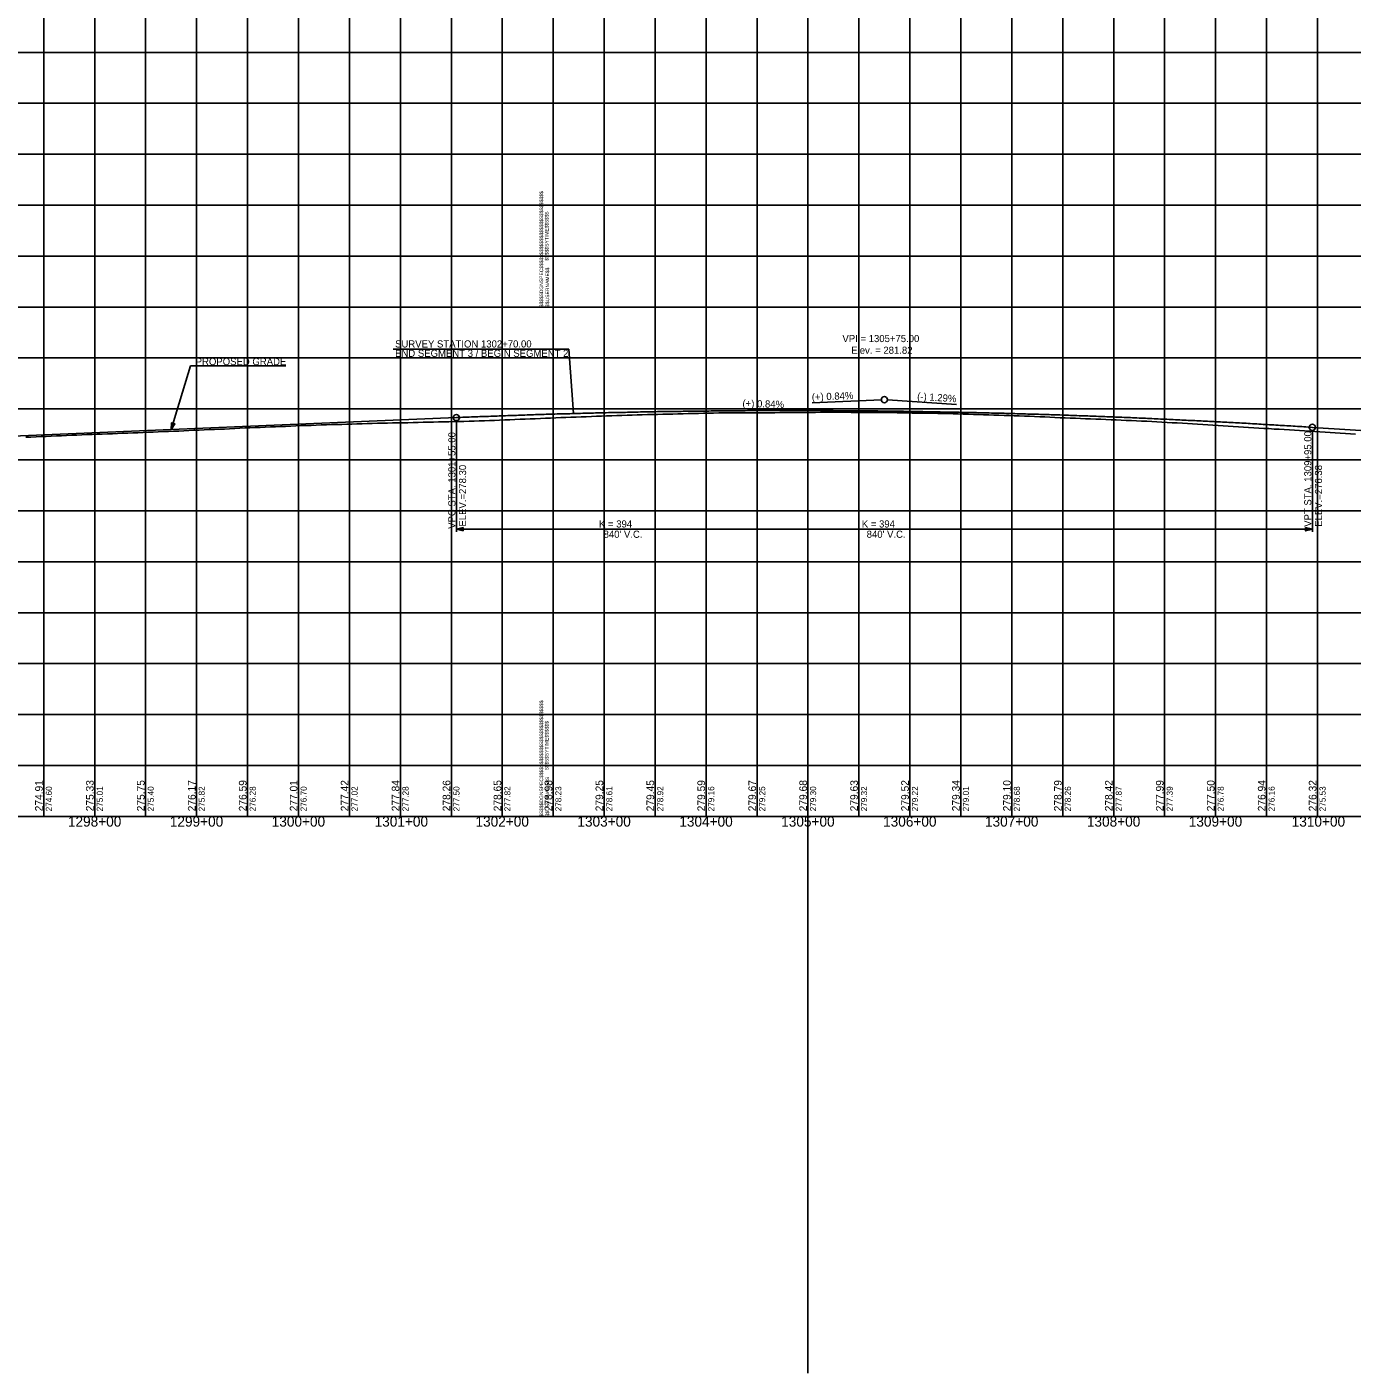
# Model space of a CAD drawing. Extents: x -90830 to 2015517, y -20856 to 836331.
# Drawn here: x 18657 to 19957, y -11344 to -10022 of the extents above; entities that cross this region are included whole.
import ezdxf

# ---------------------------------------------------------------- set-up
doc = ezdxf.new("R2010")
doc.units = 0
for name, color, linetype in [('Level 1', 7, 'Continuous'), ('RD_DDB_GradeTX', 7, 'Continuous'), ('RD_DDB_Profile_Elev', 7, 'Continuous'), ('RD_DDB_Profile_EX', 7, 'Continuous'), ('RD_DDB_Profile_Lbl', 7, 'Continuous'), ('RD_DDB_Profile_PR', 7, 'Continuous'), ('RD_DDB_StaTX', 7, 'Continuous'), ('RD_DDB_StripGrade', 7, 'Continuous'), ('RD_DDB_VCLbl', 7, 'Continuous'), ('RD_GPK_Profile_Cell', 7, 'Continuous'), ('RD_PD_Final_TX', 7, 'Continuous'), ('RD_TX_Drainage', 7, 'Continuous')]:
    doc.layers.add(name, color=color, linetype=linetype)

msp = doc.modelspace()

# ---------------------------------------------------------------- linework, layer by layer
at = {"layer": 'Level 1'}
for p, q in [((19423.5, -3180.8), (19423.5, -11343.5)), ((18673.5, -9797.1), (18673.5, -10297.1)), ((18723.5, -9797.1), (18723.5, -10297.1)), ((18773.5, -9797.1), (18773.5, -10297.1)), ((18823.5, -9797.1), (18823.5, -10297.1)), ((18873.5, -9797.1), (18873.5, -10297.1)), ((18923.5, -9797.1), (18923.5, -10297.1)), ((18973.5, -9797.1), (18973.5, -10297.1)), ((19023.5, -9797.1), (19023.5, -10297.1)), ((19073.5, -9797.1), (19073.5, -10297.1)), ((19123.5, -9797.1), (19123.5, -10297.1)), ((19173.5, -9797.1), (19173.5, -10297.1)), ((19173.5, -9797.1), (19173.5, -10297.1)), ((19173.5, -9797.1), (19173.5, -10297.1)), ((19223.5, -9797.1), (19223.5, -10297.1)), ((19273.5, -9797.1), (19273.5, -10297.1)), ((19323.5, -9797.1), (19323.5, -10297.1)), ((19373.5, -9797.1), (19373.5, -10297.1)), ((19423.5, -9797.1), (19423.5, -10297.1)), ((19473.5, -9797.1), (19473.5, -10297.1)), ((19523.5, -9797.1), (19523.5, -10297.1)), ((19573.5, -9797.1), (19573.5, -10297.1)), ((19623.5, -9797.1), (19623.5, -10297.1)), ((19673.5, -9797.1), (19673.5, -10297.1)), ((19723.5, -9797.1), (19723.5, -10297.1)), ((19773.5, -9797.1), (19773.5, -10297.1)), ((19823.5, -9797.1), (19823.5, -10297.1)), ((19873.5, -9797.1), (19873.5, -10297.1)), ((19923.5, -9797.1), (19923.5, -10297.1)), ((17573.5, -10047.1), (19173.5, -10047.1)), ((19173.5, -10047.1), (20773.5, -10047.1)), ((17573.5, -10097.1), (19173.5, -10097.1)), ((19173.5, -10097.1), (20773.5, -10097.1)), ((17573.5, -10147.1), (19173.5, -10147.1)), ((19173.5, -10147.1), (20773.5, -10147.1)), ((17573.5, -10197.1), (19173.5, -10197.1)), ((19173.5, -10197.1), (20773.5, -10197.1)), ((17573.5, -10247.1), (19173.5, -10247.1)), ((19173.5, -10247.1), (20773.5, -10247.1)), ((17573.5, -10297.1), (19173.5, -10297.1)), ((17573.5, -10297.1), (19173.5, -10297.1)), ((18673.5, -10297.1), (18673.5, -10797.1)), ((18723.5, -10297.1), (18723.5, -10797.1)), ((18773.5, -10297.1), (18773.5, -10797.1)), ((18823.5, -10297.1), (18823.5, -10797.1)), ((18873.5, -10297.1), (18873.5, -10797.1)), ((18923.5, -10297.1), (18923.5, -10797.1)), ((18973.5, -10297.1), (18973.5, -10797.1)), ((19023.5, -10297.1), (19023.5, -10797.1)), ((19073.5, -10297.1), (19073.5, -10797.1)), ((19123.5, -10297.1), (19123.5, -10797.1)), ((19173.5, -10297.1), (20773.5, -10297.1)), ((19173.5, -10297.1), (19173.5, -10797.1)), ((19173.5, -10297.1), (19173.5, -10797.1)), ((19173.5, -10297.1), (20773.5, -10297.1)), ((19173.5, -10297.1), (19173.5, -10797.1)), ((19223.5, -10297.1), (19223.5, -10797.1)), ((19273.5, -10297.1), (19273.5, -10797.1)), ((19323.5, -10297.1), (19323.5, -10797.1)), ((19373.5, -10297.1), (19373.5, -10797.1)), ((19423.5, -10297.1), (19423.5, -10797.1)), ((19473.5, -10297.1), (19473.5, -10797.1)), ((19523.5, -10297.1), (19523.5, -10797.1)), ((19573.5, -10297.1), (19573.5, -10797.1)), ((19623.5, -10297.1), (19623.5, -10797.1)), ((19673.5, -10297.1), (19673.5, -10797.1)), ((19723.5, -10297.1), (19723.5, -10797.1)), ((19773.5, -10297.1), (19773.5, -10797.1)), ((19823.5, -10297.1), (19823.5, -10797.1)), ((19873.5, -10297.1), (19873.5, -10797.1)), ((19923.5, -10297.1), (19923.5, -10797.1)), ((17573.5, -10347.1), (19173.5, -10347.1)), ((19173.5, -10347.1), (20773.5, -10347.1)), ((17573.5, -10397.1), (19173.5, -10397.1)), ((19173.5, -10397.1), (20773.5, -10397.1)), ((17573.5, -10447.1), (19173.5, -10447.1)), ((19173.5, -10447.1), (20773.5, -10447.1)), ((17573.5, -10497.1), (19173.5, -10497.1)), ((19173.5, -10497.1), (20773.5, -10497.1)), ((17573.5, -10547.1), (19173.5, -10547.1)), ((19173.5, -10547.1), (20773.5, -10547.1)), ((17573.5, -10597.1), (19173.5, -10597.1)), ((19173.5, -10597.1), (20773.5, -10597.1)), ((17573.5, -10647.1), (19173.5, -10647.1)), ((19173.5, -10647.1), (20773.5, -10647.1)), ((17573.5, -10697.1), (19173.5, -10697.1)), ((19173.5, -10697.1), (20773.5, -10697.1)), ((17573.5, -10747.1), (19173.5, -10747.1)), ((19173.5, -10747.1), (20773.5, -10747.1)), ((17573.5, -10797.1), (19173.5, -10797.1)), ((19173.5, -10797.1), (20773.5, -10797.1))]:
    msp.add_line(p, q, dxfattribs=at)
at = {"layer": 'RD_DDB_GradeTX'}
for p, q in [((19427.5, -10391), (19495.5, -10388.1)), ((19569.3, -10392.6), (19501.5, -10388.2))]:
    msp.add_line(p, q, dxfattribs=at)
msp.add_circle((19498.5, -10388), 3, dxfattribs=at)
at = {"layer": 'RD_DDB_Profile_EX'}
for points in [[(18655.9, -10424.9), (18660.9, -10424.7), (18665.9, -10424.4), (18670.9, -10424.2), (18675.9, -10424), (18680.9, -10423.8), (18685.9, -10423.6), (18690.9, -10423.4), (18695.9, -10423.2), (18700.9, -10422.9), (18705.9, -10422.7), (18710.9, -10422.5), (18715.9, -10422.3), (18720.9, -10422.1), (18725.9, -10422), (18730.9, -10421.8), (18735.9, -10421.6), (18740.9, -10421.4), (18745.9, -10421.2), (18750.9, -10421), (18755.9, -10420.8), (18760.9, -10420.6), (18765.9, -10420.4), (18770.9, -10420.2), (18775.9, -10420), (18780.9, -10419.8), (18785.9, -10419.6), (18790.9, -10419.4), (18795.9, -10419.2), (18800.9, -10419), (18805.9, -10418.8), (18810.9, -10418.6), (18815.9, -10418.4), (18820.9, -10418.1), (18825.9, -10417.9), (18830.9, -10417.7), (18835.9, -10417.4), (18840.9, -10417.2), (18845.9, -10417), (18850.9, -10416.8), (18855.9, -10416.5), (18860.9, -10416.3), (18865.9, -10416.1), (18870.9, -10415.8), (18875.9, -10415.6), (18880.9, -10415.4), (18885.9, -10415.2), (18890.9, -10415), (18895.9, -10414.8), (18900.9, -10414.6), (18905.9, -10414.4), (18910.9, -10414.2), (18915.9, -10413.9), (18920.9, -10413.7), (18925.9, -10413.5), (18930.9, -10413.3), (18935.9, -10413.2), (18940.9, -10413), (18945.9, -10412.8), (18950.9, -10412.7), (18955.9, -10412.5), (18960.9, -10412.4), (18965.9, -10412.3), (18970.9, -10412.1), (18975.9, -10412), (18980.9, -10411.8), (18985.9, -10411.6), (18990.9, -10411.5), (18995.9, -10411.3), (19000.9, -10411.2), (19005.9, -10411.1), (19010.9, -10411), (19015.9, -10410.9), (19020.9, -10410.8), (19025.9, -10410.7), (19030.9, -10410.6), (19035.9, -10410.5), (19040.9, -10410.3), (19045.9, -10410.2)], [(19045.9, -10410.2), (19050.9, -10410.1), (19055.9, -10410), (19060.9, -10409.9), (19065.9, -10409.8), (19070.9, -10409.7), (19075.9, -10409.5), (19080.9, -10409.4), (19085.9, -10409.3), (19090.9, -10409.2), (19095.9, -10409.1), (19100.9, -10408.9), (19105.9, -10408.7), (19110.9, -10408.6), (19115.9, -10408.3), (19120.9, -10408.1), (19125.9, -10407.9), (19130.9, -10407.7), (19135.9, -10407.5), (19140.9, -10407.3), (19145.9, -10407.1), (19150.9, -10406.9), (19155.9, -10406.7), (19160.9, -10406.5), (19165.9, -10406.3), (19170.9, -10406.1), (19175.9, -10405.8), (19180.9, -10405.6), (19185.9, -10405.4), (19190.9, -10405.2), (19195.9, -10405.1), (19200.9, -10405), (19205.9, -10404.8), (19210.9, -10404.5), (19215.9, -10404.3), (19220.9, -10404.1), (19225.9, -10404), (19230.9, -10403.8), (19235.9, -10403.6), (19240.9, -10403.5), (19245.9, -10403.3), (19250.9, -10403.1), (19255.9, -10403), (19260.9, -10402.9), (19265.9, -10402.7), (19270.9, -10402.6), (19275.9, -10402.5), (19280.9, -10402.3), (19285.9, -10402.2), (19290.9, -10402.1), (19295.9, -10402), (19300.9, -10401.8), (19305.9, -10401.7), (19310.9, -10401.6), (19315.9, -10401.5), (19320.9, -10401.3), (19325.9, -10401.2), (19330.9, -10401.1), (19335.9, -10401), (19340.9, -10401), (19345.9, -10400.9), (19350.9, -10400.8), (19355.9, -10400.8), (19360.9, -10400.8), (19365.9, -10400.8), (19370.9, -10400.9), (19375.9, -10400.9), (19380.9, -10400.9), (19385.9, -10400.8), (19390.9, -10400.8), (19395.9, -10400.7), (19400.9, -10400.7), (19405.9, -10400.7), (19410.9, -10400.7), (19415.9, -10400.7), (19420.9, -10400.6), (19425.9, -10400.6), (19430.9, -10400.5), (19435.9, -10400.4), (19440.9, -10400.4), (19445.9, -10400.4), (19450.9, -10400.4), (19455.9, -10400.4), (19460.9, -10400.4), (19465.9, -10400.5), (19470.9, -10400.5), (19475.9, -10400.5), (19480.9, -10400.5), (19485.9, -10400.6), (19490.9, -10400.6), (19495.9, -10400.6), (19500.9, -10400.7), (19505.9, -10400.7), (19510.9, -10400.8), (19515.9, -10400.9), (19520.9, -10401), (19525.9, -10401.1), (19530.9, -10401.1), (19535.9, -10401.2), (19540.9, -10401.3), (19545.9, -10401.4)], [(19545.9, -10401.4), (19550.9, -10401.5), (19555.9, -10401.6), (19560.9, -10401.7), (19565.9, -10401.9), (19570.9, -10402), (19575.9, -10402.2), (19580.9, -10402.3), (19585.9, -10402.5), (19590.9, -10402.7), (19595.9, -10402.9), (19600.9, -10403), (19605.9, -10403.2), (19610.9, -10403.3), (19615.9, -10403.5), (19620.9, -10403.6), (19625.9, -10403.8), (19630.9, -10404), (19635.9, -10404.2), (19640.9, -10404.3), (19645.9, -10404.6), (19650.9, -10404.8), (19655.9, -10405), (19660.9, -10405.2), (19665.9, -10405.4), (19670.9, -10405.7), (19675.9, -10405.9), (19680.9, -10406.1), (19685.9, -10406.3), (19690.9, -10406.5), (19695.9, -10406.7), (19700.9, -10406.9), (19705.9, -10407.1), (19710.9, -10407.3), (19715.9, -10407.5), (19720.9, -10407.7), (19725.9, -10407.9), (19730.9, -10408.1), (19735.9, -10408.3), (19740.9, -10408.5), (19745.9, -10408.7), (19750.9, -10409), (19755.9, -10409.2), (19760.9, -10409.5), (19765.9, -10409.7), (19770.9, -10410), (19775.9, -10410.3), (19780.9, -10410.6), (19785.9, -10410.9), (19790.9, -10411.2), (19795.9, -10411.5), (19800.9, -10411.8), (19805.9, -10412.1), (19810.9, -10412.4), (19815.9, -10412.7), (19820.9, -10413), (19825.9, -10413.4), (19830.9, -10413.7), (19835.9, -10414), (19840.9, -10414.3), (19845.9, -10414.6), (19850.9, -10414.9), (19855.9, -10415.2), (19860.9, -10415.6), (19865.9, -10415.9), (19870.9, -10416.2), (19875.9, -10416.4), (19880.9, -10416.8), (19885.9, -10417.1), (19890.9, -10417.4), (19895.9, -10417.7), (19900.9, -10418), (19905.9, -10418.3), (19910.9, -10418.6), (19915.9, -10419), (19920.9, -10419.3), (19925.9, -10419.6), (19930.9, -10420), (19935.9, -10420.3), (19940.9, -10420.6), (19945.9, -10420.9), (19950.9, -10421.2), (19955.9, -10421.5), (19960.9, -10421.8)]]:
    msp.add_lwpolyline(points, dxfattribs=at)
at = {"layer": 'RD_DDB_Profile_Lbl'}
for p in [(19016.3, -10338.4), (19193.5, -10401.6)]:
    msp.add_line(p, (19188.8, -10338.4), dxfattribs=at)
at = {"layer": 'RD_DDB_Profile_PR'}
for p, q in [((16833.5, -10499.6), (19078.5, -10405.6)), ((19918.5, -10415.2), (21173.5, -10496.5))]:
    msp.add_line(p, q, dxfattribs=at)
msp.add_spline([(19078.5, -10405.6), (19095.3, -10404.9), (19112.1, -10404.3), (19128.9, -10403.7), (19145.7, -10403.1), (19162.5, -10402.5), (19179.3, -10402), (19196.1, -10401.6), (19212.9, -10401.1), (19229.7, -10400.7), (19246.5, -10400.4), (19263.3, -10400), (19280.1, -10399.7), (19296.9, -10399.5), (19313.7, -10399.3), (19330.5, -10399.1), (19347.3, -10398.9), (19364.1, -10398.8), (19380.9, -10398.7), (19397.7, -10398.7), (19414.5, -10398.7), (19431.3, -10398.7), (19448.1, -10398.8), (19464.9, -10398.9), (19481.7, -10399), (19498.5, -10399.2), (19515.3, -10399.4), (19532.1, -10399.7), (19548.9, -10400), (19565.7, -10400.3), (19582.5, -10400.6), (19599.3, -10401), (19616.1, -10401.4), (19632.9, -10401.9), (19649.7, -10402.4), (19666.5, -10402.9), (19683.3, -10403.5), (19700.1, -10404.1), (19716.9, -10404.7), (19733.7, -10405.4), (19750.5, -10406.1), (19767.3, -10406.9), (19784.1, -10407.7), (19800.9, -10408.5), (19817.7, -10409.3), (19834.5, -10410.2), (19851.3, -10411.1), (19868.1, -10412.1), (19884.9, -10413.1), (19901.7, -10414.1), (19918.5, -10415.2)], degree=3, dxfattribs=at)
at = {"layer": 'RD_DDB_VCLbl'}
for p, q in [((19078.5, -10517.7), (19078.5, -10408.6)), ((19918.5, -10517.7), (19918.5, -10418.2)), ((19078.5, -10515.2), (19918.5, -10515.2))]:
    msp.add_line(p, q, dxfattribs=at)
for centre in [(19078.5, -10405.6), (19918.5, -10415.2)]:
    msp.add_circle(centre, 3, dxfattribs=at)
at = {"layer": 'RD_GPK_Profile_Cell'}
msp.add_line((4823.5, -10797.1), (75223.5, -10797.1), dxfattribs=at)
at = {"layer": 'RD_PD_Final_TX'}
for p, q in [((18798.6, -10417.3), (18798.9, -10410.6)), ((18800.5, -10411.1), (18798.6, -10417.3)), ((18798.6, -10417.3), (18802, -10411.6)), ((18798.9, -10410.6), (18802, -10411.6))]:
    msp.add_line(p, q, dxfattribs=at)
for points in [[(18911, -10354.9), (18817.6, -10354.9), (18798.6, -10417.3)], [(18800.4, -10411.2), (18798.7, -10416.9), (18800.4, -10411.1), (18798.7, -10416.7), (18800.3, -10411.1), (18798.7, -10416.5), (18800.2, -10411.1), (18798.7, -10416.2), (18800.2, -10411.1), (18798.7, -10415.9), (18800.1, -10411.1), (18798.7, -10415.5), (18800, -10411.1), (18798.8, -10415.2), (18799.9, -10411), (18798.8, -10414.9), (18799.9, -10411), (18798.8, -10414.6), (18799.8, -10411), (18798.8, -10414.3), (18799.7, -10411), (18798.8, -10414), (18799.6, -10410.9), (18798.9, -10413.5), (18799.6, -10410.9), (18798.8, -10413.2), (18799.5, -10410.9), (18798.9, -10412.8), (18799.4, -10410.9), (18798.9, -10412.4), (18799.3, -10410.8), (18798.9, -10412.1), (18799.3, -10410.8), (18798.9, -10411.8), (18799.2, -10410.8), (18799, -10411.4), (18799.1, -10410.8), (18799, -10411), (18799, -10410.8)], [(18798.8, -10416.9), (18800.5, -10411.2), (18798.9, -10416.7), (18800.6, -10411.2), (18799, -10416.6), (18800.6, -10411.2), (18799.1, -10416.4), (18800.7, -10411.2), (18799.2, -10416.2), (18800.8, -10411.3), (18799.3, -10416), (18800.8, -10411.3), (18799.5, -10415.8), (18800.9, -10411.3), (18799.6, -10415.5), (18801, -10411.3), (18799.7, -10415.3), (18801, -10411.3), (18799.9, -10415), (18801.1, -10411.3), (18800, -10414.8), (18801.1, -10411.4), (18800.2, -10414.5), (18801.2, -10411.4), (18800.4, -10414.2), (18801.3, -10411.4), (18800.5, -10414), (18801.3, -10411.4), (18800.7, -10413.7), (18801.4, -10411.4), (18800.9, -10413.4), (18801.4, -10411.5), (18801, -10413.1), (18801.5, -10411.5), (18801.2, -10412.9), (18801.6, -10411.6), (18801.4, -10412.5), (18801.7, -10411.5), (18801.5, -10412.3), (18801.8, -10411.6), (18801.6, -10412.2), (18801.8, -10411.7), (18801.9, -10411.6), (18801.8, -10411.7)]]:
    msp.add_lwpolyline(points, dxfattribs=at)
at = {"layer": 'RD_TX_Drainage'}
for points in [[(19085.1, -10516.9), (19078.5, -10515.2), (19085.1, -10513.6)], [(19911.9, -10513.6), (19918.5, -10515.2), (19911.9, -10516.9)]]:
    msp.add_lwpolyline(points, close=True, dxfattribs=at)

# ---------------------------------------------------------------- texts
at = {"layer": 'Level 1'}
for s, p in [('$$$$$DGNSPEC$$$$$$$$$$$$$$$$$$$$$$$$$$$$', (19163.6, -10297.2)), ('$$$$$SYTIME$$$$$$', (19168.9, -10251.6)), ('$$USERNAME$$', (19169.5, -10297)), ('$$$$$DGNSPEC$$$$$$$$$$$$$$$$$$$$$$$$$$$$', (19163.6, -10797.2)), ('$$$$$SYTIME$$$$$$', (19168.9, -10751.6)), ('$$USERNAME$$', (19169.5, -10797))]:
    msp.add_text(s, height=3.544, rotation=90, dxfattribs=at).set_placement(p)
at = {"layer": 'RD_DDB_GradeTX'}
for s, rotation, p in [('(+) 0.84%', 2.397, (19427.4, -10389)), ('(-) 1.29%', 356.2961, (19530.5, -10388.1)), ('(+) 0.84%', 358.2907, (19359.1, -10395))]:
    msp.add_text(s, height=7, rotation=rotation, dxfattribs=at).set_placement(p)
at = {"layer": 'RD_DDB_Profile_Elev'}
for s, p in [('274.91', (18672.5, -10792.1)), ('275.33', (18722.5, -10792.1)), ('275.75', (18772.5, -10792.1)), ('276.17', (18822.5, -10792.1)), ('276.59', (18872.5, -10792.1)), ('277.01', (18922.5, -10792.1)), ('277.42', (18972.5, -10792.1)), ('277.84', (19022.5, -10792.1)), ('278.26', (19072.5, -10792.1)), ('278.65', (19122.5, -10792.1)), ('278.98', (19172.5, -10792.1)), ('279.25', (19222.5, -10792.1)), ('279.45', (19272.5, -10792.1)), ('279.59', (19322.5, -10792.1)), ('279.67', (19372.5, -10792.1)), ('279.68', (19422.5, -10792.1)), ('279.63', (19472.5, -10792.1)), ('279.52', (19522.5, -10792.1)), ('279.34', (19572.5, -10792.1)), ('279.10', (19622.5, -10792.1)), ('278.79', (19672.5, -10792.1)), ('278.42', (19722.5, -10792.1)), ('277.99', (19772.5, -10792.1)), ('277.50', (19822.5, -10792.1)), ('276.94', (19872.5, -10792.1)), ('276.32', (19922.5, -10792.1))]:
    msp.add_text(s, height=7.5, rotation=90, dxfattribs=at).set_placement(p)
at = {"layer": 'RD_DDB_Profile_Lbl'}
for s, p in [('SURVEY STATION 1302+70.00', (19018.3, -10336.8)), ('VPI = 1305+75.00', (19457.3, -10331.5)), ('END SEGMENT 3 / BEGIN SEGMENT 2', (19018.3, -10346)), ('Elev. = 281.82', (19466, -10343))]:
    msp.add_text(s, height=7, dxfattribs=at).set_placement(p)
at = {"layer": 'RD_DDB_StaTX'}
for s, p in [('1298+00', (18697.2, -10807.1)), ('1299+00', (18797.2, -10807.1)), ('1300+00', (18897.2, -10807.1)), ('1301+00', (18998.2, -10807.1)), ('1302+00', (19097.2, -10807.1)), ('1303+00', (19197.2, -10807.1)), ('1304+00', (19297.2, -10807.1)), ('1305+00', (19397.2, -10807.1)), ('1306+00', (19497.2, -10807.1)), ('1307+00', (19597.2, -10807.1)), ('1308+00', (19697.2, -10807.1)), ('1309+00', (19797.2, -10807.1)), ('1310+00', (19898.2, -10807.1))]:
    msp.add_text(s, height=10, dxfattribs=at).set_placement(p)
at = {"layer": 'RD_DDB_StripGrade'}
for s, height, p in [('VPC STA. 1301+55.00 ', 7, (19077.5, -10514.8)), ('VPT STA. 1309+95.00 ', 7, (19917.5, -10512.8)), ('ELEV.=278.30', 7, (19088, -10512.6)), ('ELEV.=276.38', 7, (19928, -10512.8)), ('274.60', 6, (18681.5, -10792.1)), ('275.01', 6, (18731.5, -10792.1)), ('275.40', 6, (18781.5, -10792.1)), ('275.82', 6, (18831.5, -10792.1)), ('276.28', 6, (18881.5, -10792.1)), ('276.70', 6, (18931.5, -10792.1)), ('277.02', 6, (18981.5, -10792.1)), ('277.28', 6, (19031.5, -10792.1)), ('277.50', 6, (19081.5, -10792.1)), ('277.82', 6, (19131.5, -10792.1)), ('278.23', 6, (19181.5, -10792.1)), ('278.61', 6, (19231.5, -10792.1)), ('278.92', 6, (19281.5, -10792.1)), ('279.16', 6, (19331.5, -10792.1)), ('279.25', 6, (19381.5, -10792.1)), ('279.30', 6, (19431.5, -10792.1)), ('279.32', 6, (19481.5, -10792.1)), ('279.22', 6, (19531.5, -10792.1)), ('279.01', 6, (19581.5, -10792.1)), ('278.68', 6, (19631.5, -10792.1)), ('278.26', 6, (19681.5, -10792.1)), ('277.87', 6, (19731.5, -10792.1)), ('277.39', 6, (19781.5, -10792.1)), ('276.78', 6, (19831.5, -10792.1)), ('276.16', 6, (19881.5, -10792.1)), ('275.53', 6, (19931.5, -10792.1))]:
    msp.add_text(s, height=height, rotation=90, dxfattribs=at).set_placement(p)
at = {"layer": 'RD_DDB_VCLbl'}
for s, p in [('K = 394', (19218.4, -10513.5)), ("840' V.C.", (19222.9, -10523.6)), ('K = 394', (19476.3, -10513.5)), ("840' V.C.", (19481.1, -10523.6))]:
    msp.add_text(s, height=7, dxfattribs=at).set_placement(p)
at = {"layer": 'RD_PD_Final_TX'}
msp.add_text('PROPOSED GRADE', height=7, dxfattribs=at).set_placement((18822.6, -10354.1))

doc.saveas('drawing.dxf')
